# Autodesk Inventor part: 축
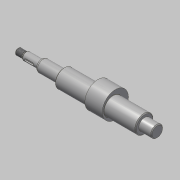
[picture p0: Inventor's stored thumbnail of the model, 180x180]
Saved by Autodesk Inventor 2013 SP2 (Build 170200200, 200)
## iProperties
Created: 2015-12
Part Number: 축
Document SubType Name: Modeling
Designer: mdu
Density: 7.86 g/cm^3
Material: 강철, 연강
Author: mdu
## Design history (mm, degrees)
sketch "스케치1"
  geometry: L1 (62, 100.9)-(62, 67.1) reference; L2 (51, 101.2)-(51, 84) reference; L3 (-51, 84)-(-51, 101.2) reference; L4 (-62, 67.1)-(-62, 100.9) reference; L5 (-51.6, 91.5)-(-61.4, 91.5) reference; L6 (51.6, 91.5)-(61.4, 91.5) reference; L7 (67, 84)-(-109, 84); L8 (-77, 64.201)-(-77, 103.799) reference; L9 (67, 84)-(67, 91.5); L10 (67, 91.5)-(51, 91.5); L11 (51, 91.5)-(51, 95.5); L12 (51, 95.5)-(-51, 95.5); L13 (-51, 95.5)-(-51, 91.5); L14 (-51, 91.5)-(-79, 91.5); L15 (-79, 91.5)-(-79, 89); L16 (-79, 89)-(-99, 89); L17 (-99, 89)-(-99, 87); L18 (-100.5, 88)-(-109, 88); L19 (-109, 88)-(-109, 84); L20 (-99, 87)-(-100.5, 87); L21 (-100.5, 87)-(-100.5, 88); 2 further points
  constraints: 32 end point, 7 parallel, 6 point on line, 5 perpendicular, 2 collinear, 2 horizontal, 1 midpoint, 4 other
  dimensions: "d0" = 5 distance from line of L7.start L1; "d2" = 2 distance between parallel lines of L15 L8; "d3" = 23 diameter of L12 L7; "d4" = 10 diameter of L16 L7; "d5" = 1.5 distance of L17.end L20.end; "d6" = 6 diameter of L20 L7; "d7" = 20 distance of L15.end L16.end; "d8" = 10 distance between parallel lines of L17 L19; "d9" = 8 diameter of L18 L7
revolve "회전1" sketch "스케치1" stored, may be unused: angle "d10" = 90 deg
sketch "스케치2"
  geometry: C1 r 11.5 at (84, 0) reference; C2 r 11.5 at (84, 0) reference; C3 r 16.5 at (87, 0); 1 further point
  constraints: 1 centre point, 1 horizontal alignment
  dimensions: "d11" = 33 diameter of C3; "d12" = 3 distance of C3.centre C1.centre
extrude "돌출1" join sketch "스케치2" stored distance "d13" = 22; taper "d14" = 0 deg
chamfer "모따기1" distance "d15" = 1; stored, may be unused: second distance "d16" = 2, angle "d17" = 45 deg
feature "스레드1" dims "d18" = 10, "d19" = 0
node "작업 평면1"
sketch "스케치3"
  geometry: L1 (-5.5, -1.5)-(3.5, -1.5); L2 (3.5, 1.5)-(-5.5, 1.5); L3 (-10, -4)-(-10, 4) reference; A1 r 1.5 centre (3.5, 0) between (3.5, -1.5) and (3.5, 1.5); A2 r 1.5 centre (-5.5, 0) between (-5.5, 1.5) and (-5.5, -1.5); 2 further points
  constraints: 4 end point, 4 point on circle, 4 tangent, 2 centre point, 1 horizontal, 1 horizontal alignment, 1 midpoint, 1 parallel
  dimensions: "d20" = 3 distance between parallel lines of L1 L2; "d21" = 12 dimension on A1 A2; "d22" = 3 distance edge to line of A2 L3
extrude "돌출2" cut sketch "스케치3" distance "d23" = 1.8; taper "d24" = 0 deg
fillet "모깎기1" dims "d25" = 0.3
fillet "모깎기2" dims "d26" = 3
node "솔리드1"
node "참조1"
node "참조2"
node "참조3"
node "참조4"
node "참조5"
node "투영된 루프1"
